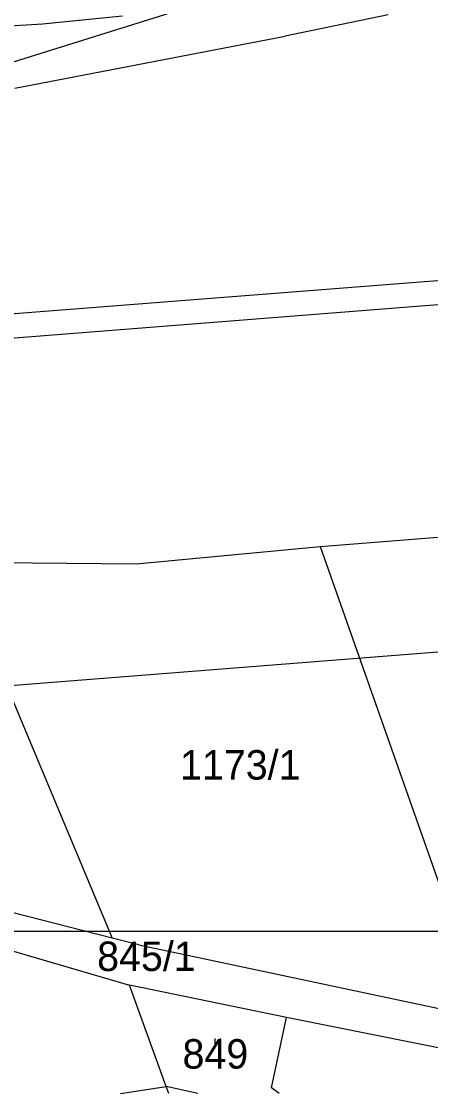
# Model space of a CAD drawing. Extents: x -510185 to -506993, y -1126306 to -1123642.
# Drawn here: x -509243.9 to -509173.1, y -1126306.3 to -1126120.6 of the extents above; entities that cross this region are included whole.
import ezdxf

# ---------------------------------------------------------------- set-up
doc = ezdxf.new("R2010")
doc.units = 0
for name, color, linetype in [('ochranná pásma', 7, 'Continuous'), ('parcelni hranice', 7, 'Continuous'), ('u_dráha', 7, 'Continuous'), ('u_kabely', 7, 'Continuous'), ('x_formát_rám', 7, 'Continuous'), ('ˇ2', 7, 'Continuous'), ('ˇ3', 7, 'Continuous')]:
    doc.layers.add(name, color=color, linetype=linetype)

msp = doc.modelspace()

# ---------------------------------------------------------------- linework, layer by layer
at = {"layer": 'ochranná pásma'}
msp.add_line((-509290.98, -1126239.2), (-509113.69, -1126225.24), dxfattribs=at)
at = {"layer": 'parcelni hranice'}
for p, q in [((-509248.18, -1126128.53), (-509213.38, -1126117.64)), ((-509180.44, -1126119.53), (-509198.31, -1126123.18)), ((-509245.11, -1126132.22), (-509198.31, -1126123.18)), ((-509192.21, -1126211.55), (-509159.17, -1126208.99)), ((-509224.07, -1126214.57), (-509192.21, -1126211.55)), ((-509192.21, -1126211.55), (-509163.47, -1126293.29)), ((-509255.47, -1126214.3), (-509224.07, -1126214.57)), ((-509255.47, -1126214.3), (-509228.22, -1126279.4)), ((-509228.22, -1126279.4), (-509270.82, -1126268.49)), ((-509272.3, -1126273.72), (-509225.23, -1126287.54)), ((-509223.64, -1126280.57), (-509228.22, -1126279.4)), ((-509223.64, -1126280.57), (-509163.47, -1126293.29)), ((-509218.86, -1126305.08), (-509225.23, -1126287.54)), ((-509198.06, -1126293.16), (-509225.23, -1126287.54)), ((-509200.66, -1126305.32), (-509198.06, -1126293.16)), ((-509165.25, -1126299.71), (-509198.06, -1126293.16)), ((-509226.77, -1126306.31), (-509218.86, -1126305.08)), ((-509213.38, -1126306.31), (-509218.86, -1126305.08)), ((-509218.41, -1126306.31), (-509218.86, -1126305.08)), ((-509199.33, -1126306.31), (-509200.66, -1126305.32))]:
    msp.add_line(p, q, dxfattribs=at)
at = {"layer": 'u_dráha'}
for p, q in [((-509296.05, -1126175.17), (-509120.65, -1126161.53)), ((-509295.69, -1126179.39), (-509118.4, -1126165.43))]:
    msp.add_line(p, q, dxfattribs=at)
at = {"layer": 'u_kabely'}
msp.add_lwpolyline([(-509264.1, -1126122.51), (-509240.27, -1126121.06), (-509226.47, -1126119.7)], dxfattribs=at)
at = {"layer": 'x_formát_rám'}
msp.add_lwpolyline([(-510158.52, -1126278.21), (-507008.52, -1126278.21), (-507008.52, -1123673.61), (-510158.52, -1123673.61)], close=True, dxfattribs=at)
at = {"layer": 'ˇ3'}
for points in [[(-509210.49, -1126296.78), (-509210.49, -1126298.28)], [(-509209.49, -1126298.28), (-509209.49, -1126296.78)]]:
    msp.add_lwpolyline(points, dxfattribs=at)

# ---------------------------------------------------------------- texts
at = {"layer": 'ˇ2'}
for s, p in [('1173/1', (-509216.49, -1126251.94)), ('845/1', (-509230.84, -1126285.09)), ('849', (-509216.06, -1126301.99))]:
    msp.add_text(s, height=5.1, dxfattribs=at).set_placement(p)

doc.saveas('drawing.dxf')
